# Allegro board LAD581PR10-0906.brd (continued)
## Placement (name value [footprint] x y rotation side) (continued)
CG339  1U_0402_6.3V4Z  [C_0402]  239.08 91.53 0 top
CG340  1U_0402_6.3V4Z  [C_0402]  219.03 130.69 90 top
CG341  1U_0402_6.3V4Z  [C_0402]  186.26 130.12 90 top
CG342  1U_0402_6.3V4Z  [C_0402]  220.11 129.7 270 top
CG343  1U_0402_6.3V4Z  [C_0402]  241.31 98.88 90 top
CG344  22U_0603_6.3V6M  [C_0603]  243.35 78.26 90 bottom
CG345  10U_0402_6.3V4Z  [C_0402]  221.32 140.23 180 top
CG346  10U_0402_6.3V4Z  [C_0402]  185.18 133.11 90 top
CG347  10U_0402_6.3V4Z  [C_0402]  238.53 106.01 180 top
CG348  1U_0402_6.3V4Z  [C_0402]  187.4 131.08 90 top
CG349  1U_0402_6.3V4Z  [C_0402]  242.39 94.59 270 top
CG350  1U_0402_6.3V4Z  [C_0402]  204.67 138.25 90 top
CG351  1U_0402_6.3V4Z  [C_0402]  237.43 80.29 0 top
CG352  1U_0402_6.3V4Z  [C_0402]  222.14 130.69 90 top
CG353  1U_0402_6.3V4Z  [C_0402]  185.31 130.12 90 top
CG354  1U_0402_6.3V4Z  [C_0402]  237.89 126.15 270 top
CG355  1U_0402_6.3V4Z  [C_0402]  221.12 129.7 270 top
CG356  1U_0402_6.3V4Z  [C_0402]  239.1 97.94 180 top
CG357  1U_0402_6.3V4Z  [C_0402]  186.39 133.9 270 top
CG358  1U_0402_6.3V4Z  [C_0402]  219.03 129.7 270 top
CG359  1U_0402_6.3V4Z  [C_0402]  220.28 134.64 0 top
CG360  1U_0402_6.3V4Z  [C_0402]  205.56 138.25 90 top
CG361  1U_0402_6.3V4Z  [C_0402]  243.61 77.05 180 top
CG362  1U_0402_6.3V4Z  [C_0402]  221.06 133.7 270 top
CG363  1U_0402_6.3V4Z  [C_0402]  184.22 136.87 0 top
CG364  22U_0603_6.3V6M  [C_0603]  229.88 130.01 270 bottom
CG365  10U_0402_6.3V4Z  [C_0402]  240.63 124.67 180 top
CG366  10U_0402_6.3V4Z  [C_0402]  239.47 105.93 90 top
CG367  10U_0402_6.3V4Z  [C_0402]  238.53 106.89 180 top
CG368  1U_0402_6.3V4Z  [C_0402]  185.26 131.91 180 top
CG369  1U_0402_6.3V4Z  [C_0402]  188.53 137.12 0 top
CG370  1U_0402_6.3V4Z  [C_0402]  234.19 125.63 0 top
CG371  1U_0402_6.3V4Z  [C_0402]  186.01 138.38 90 top
CG372  1U_0402_6.3V4Z  [C_0402]  221.12 130.69 90 top
CG373  1U_0402_6.3V4Z  [C_0402]  202.95 137.12 0 top
CG374  1U_0402_6.3V4Z  [C_0402]  240.63 123.72 180 top
CG375  1U_0402_6.3V4Z  [C_0402]  187.47 130.15 270 top
CG376  1U_0402_6.3V4Z  [C_0402]  240.63 122.83 180 top
CG377  1U_0402_6.3V4Z  [C_0402]  234.95 100.16 0 top
CG378  1U_0402_6.3V4Z  [C_0402]  240.37 98.83 180 top
CG379  1U_0402_6.3V4Z  [C_0402]  241.05 89.81 0 top
CG380  1U_0402_6.3V4Z  [C_0402]  204.99 136.22 90 top
CG381  1U_0402_6.3V4Z  [C_0402]  238.77 123.52 90 top
CG382  1U_0402_6.3V4Z  [C_0402]  220.11 133.7 270 top
CG383  1U_0402_6.3V4Z  [C_0402]  237.9 99.72 180 top
CG384  0.1U_0402_10V7K  [C_0402]  123.74 158.37 180 bottom
CG385  10U_0402_6.3V6M  [C_0402]  194.97 75.51 90 top
CG386  0.1U_0402_10V7K  [C_0402]  164.37 67.72 180 top
CG388  22U_0603_6.3V6M  [C_0603]  196.48 129.18 270 bottom
CG389  22U_0603_6.3V6M  [C_0603]  195.34 133.12 0 bottom
CG390  22U_0603_6.3V6M  [C_0603]  196.74 139.47 90 bottom
CG391  10U_0402_6.3V4Z  [C_0402]  203.99 129.82 180 top
CG392  10U_0402_6.3V4Z  [C_0402]  205.37 132.04 0 top
CG393  10U_0402_6.3V4Z  [C_0402]  203.2 134.77 0 top
CG394  1U_0402_6.3V4Z  [C_0402]  205.37 130.91 270 top
CG395  1U_0402_6.3V4Z  [C_0402]  205.63 135.22 0 top
CG396  1U_0402_6.3V4Z  [C_0402]  219.36 136.42 180 top
CG397  1U_0402_6.3V4Z  [C_0402]  203.98 131.74 270 top
CG398  1U_0402_6.3V4Z  [C_0402]  201.63 137.25 180 top
CG399  1U_0402_6.3V4Z  [C_0402]  205.37 133.18 90 top
CG400  1U_0402_6.3V4Z  [C_0402]  203.91 132.87 90 top
CG401  1U_0402_6.3V4Z  [C_0402]  219.29 137.37 180 top
CG402  1U_0402_6.3V4Z  [C_0402]  204.69 141.88 180 top
CG403  1U_0402_6.3V4Z  [C_0402]  204.67 141.01 270 top
CG404  22U_0603_6.3V6M  [C_0603]  231.15 122.77 180 bottom
CG405  22U_0603_6.3V6M  [C_0603]  234.14 108.2 0 top
CG406  22U_0603_6.3V6M  [C_0603]  180.99 144.68 0 bottom
CG407  10U_0402_6.3V4Z  [C_0402]  238.95 99.72 0 top
CG408  10U_0402_6.3V4Z  [C_0402]  238.58 108.43 0 top
CG409  10U_0402_6.3V4Z  [C_0402]  234.04 121.22 90 top
CG410  1U_0402_6.3V4Z  [C_0402]  239.84 114.27 0 top
CG411  1U_0402_6.3V4Z  [C_0402]  236.06 124.62 0 top
CG412  1U_0402_6.3V4Z  [C_0402]  236.06 125.54 0 top
CG413  1U_0402_6.3V4Z  [C_0402]  234.19 124.65 0 top
CG414  1U_0402_6.3V4Z  [C_0402]  240.95 97.94 180 top
CG415  1U_0402_6.3V4Z  [C_0402]  236.82 98.83 180 top
CG416  1U_0402_6.3V4Z  [C_0402]  234.01 113.04 90 top
CG417  1U_0402_6.3V4Z  [C_0402]  234.13 98.89 0 top
CG418  1U_0402_6.3V4Z  [C_0402]  236.06 126.44 0 top
CG419  1U_0402_6.3V4Z  [C_0402]  236.04 123.7 0 top
CG420  22U_0603_6.3V6M  [C_0603]  230.96 87.65 180 bottom
CG421  22U_0603_6.3V6M  [C_0603]  237.69 106.45 0 bottom
CG422  22U_0603_6.3V6M  [C_0603]  178.13 142.01 270 bottom
CG423  10U_0402_6.3V4Z  [C_0402]  241.7 78.83 90 top
CG424  10U_0402_6.3V4Z  [C_0402]  238.9 88.68 270 top
CG425  10U_0402_6.3V4Z  [C_0402]  236.81 73.56 0 top
CG426  1U_0402_6.3V4Z  [C_0402]  239.92 80.8 0 top
CG427  1U_0402_6.3V4Z  [C_0402]  242.91 86.19 180 top
CG428  1U_0402_6.3V4Z  [C_0402]  243.47 78.82 90 top
CG429  1U_0402_6.3V4Z  [C_0402]  240.22 86.19 0 top
CG430  1U_0402_6.3V4Z  [C_0402]  239.92 79.91 0 top
CG431  1U_0402_6.3V4Z  [C_0402]  242.58 78.83 90 top
CG432  1U_0402_6.3V4Z  [C_0402]  238.25 86.19 0 top
CG433  1U_0402_6.3V4Z  [C_0402]  242.46 76.1 270 top
CG434  1U_0402_6.3V4Z  [C_0402]  236.81 72.6 0 top
CG435  1U_0402_6.3V4Z  [C_0402]  237.44 79.4 0 top
CG436  0.1U_0402_16V4Z~D  [C_0402]  174.72 61.49 180 bottom
CG437  0.1U_0402_16V4Z~D  [C_0402]  174.74 60.6 180 bottom
CG438  0.1U_0201_6.3V6K  [C_0201]  93.13 68.41 0 top
CG439  0.1U_0201_6.3V6K  [C_0201]  95.73 68.22 0 top
CG440  0.1U_0201_6.3V6K  [C_0201]  189.66 76.03 180 top
CG442  0.01U_0402_16V  [C_0402]  186.56 57.67 270 top
CG443  0.01U_0402_16V  [C_0402]  182.31 56.36 0 top
CG444  0.1U_0201_6.3V6K  [C_0201]  90.78 67.52 0 top
CG483  0.1U_0201_6.3V6K  [C_0201]  185.87 66.85 180 bottom
CG487  0.1U_0402_10V7K  [C_0402]  191.52 68.55 180 bottom
CH1  10P_0402_50V8J~D  [C_0402]  316.37 80.05 270 top
CH2  0.1U_0402_16V4Z~D  [C_0402]  314.73 84.14 180 top
CH3  0.1U_0402_10V7K  [C_0402]  177.04 46.19 0 top
CH4  0.1U_0402_10V7K  [C_0402]  170.63 38.06 0 top
CH45  8.2P_0402_50V  [C_0402]  185.04 50.17 90 bottom
CH46  8.2P_0402_50V  [C_0402]  185.04 49.24 270 bottom
CH47  15P_0402_50V  [C_0402]  158.85 56.58 180 bottom
CH48  15P_0402_50V  [C_0402]  159.73 56.58 0 bottom
CH49  0.1U_0402_16V7K~D  [C_0402]  186.74 25.45 0 bottom
CH52  1U_0603_10V6K~D  [C_0603]  181.75 45.32 270 top
CH53  1U_0603_10V6K~D  [C_0603]  182.96 50.57 0 top
CH70  0.1U_0402_10V7K~D  [C_0402]  180.59 39.7 0 top
CH80  1U_0402_6.3V6K~D  [C_0402]  177.99 42.15 180 top
CH82  1U_0402_6.3V6K~D  [C_0402]  169.11 45.93 90 top
CH100  0.022U_0402_25V7K  [C_0402]  122.99 27.48 0 top
CH101  0.022U_0402_25V7K  [C_0402]  125.67 43.47 90 top
CH102  10U_0603_6.3V6M~D  [C_0603]  138.53 96.67 270 top
CH103  10U_0603_6.3V6M~D  [C_0603]  138.53 99.08 270 top
CH104  10U_0603_6.3V6M~D  [C_0603]  138.42 101.48 90 top
CH105  1U_0402_6.3V6K~D  [C_0402]  143.09 104.89 270 top
CH106  1U_0402_6.3V6K~D  [C_0402]  141.82 104.9 270 top
CH107  1U_0402_6.3V6K~D  [C_0402]  138.46 104.71 0 top
CH108  1U_0402_6.3V6K~D  [C_0402]  138.67 106.01 180 top
CH109  1U_0402_6.3V6K~D  [C_0402]  140.36 107.87 0 top
CH110  1U_0402_6.3V6K~D  [C_0402]  138.38 103.81 0 top
CH118  22U_0603_6.3V6M  [C_0603]  116.5 91.97 90 top
CH119  10U_0603_6.3V6M~D  [C_0603]  121.24 91.85 90 top
CH120  22U_0603_6.3V6M  [C_0603]  141.98 90.58 0 top
CH121  22U_0603_6.3V6M  [C_0603]  119.13 74.5 0 top
CH122  10U_0603_6.3V6M~D  [C_0603]  122.97 91.34 90 top
CH123  10U_0603_6.3V6M~D  [C_0603]  119.13 73.23 0 top
CH124  22U_0603_6.3V6M  [C_0603]  114.85 91.97 90 top
CH125  10U_0603_6.3V6M~D  [C_0603]  126.61 90.67 90 top
CH126  10U_0603_6.3V6M~D  [C_0603]  138.75 72.34 0 top
CH127  10U_0603_6.3V6M~D  [C_0603]  135.73 91.27 90 top
CH128  10U_0603_6.3V6M~D  [C_0603]  119.13 71.96 0 top
CH129  22U_0805_6.3V6M~D  [C_0805]  138.63 75.58 0 top
CH130  22U_0805_6.3V6M~D  [C_0805]  138.63 73.86 0 top
CH131  22U_0805_6.3V6M~D  [C_0805]  124.05 72.33 180 top
CH132  22U_0805_6.3V6M~D  [C_0805]  124.05 74.17 180 top
CH173  0.1U_0402_10V7K  [C_0402]  177.99 41.26 180 top
CH174  0.1U_0402_10V  [C_0402]  175.65 48.52 90 top
CH175  0.1U_0402_10V  [C_0402]  180.91 56.29 0 bottom
CH176  1U_0402_6.3V6K~D  [C_0402]  179.31 38.75 180 top
CH177  22U_0805_6.3V6M~D  [C_0805]  168.77 55.47 0 bottom
CH178  22U_0805_6.3V6M~D  [C_0805]  165.91 55.48 0 bottom
CH179  1U_0402_6.3V6K~D  [C_0402]  164.92 55.02 90 bottom
CH180  1U_0402_6.3V6K~D  [C_0402]  163.2 42.31 90 top
CH181  22U_0805_6.3V6M~D  [C_0805]  158.72 39.02 180 top
CH182  22U_0805_6.3V6M~D  [C_0805]  158.72 40.8 180 top
CH183  1U_0402_6.3V6K~D  [C_0402]  167.52 39.67 270 top
CH184  22U_0805_6.3V6M~D  [C_0805]  158.67 42.56 180 top
CH185  1U_0402_6.3V6K~D  [C_0402]  171.41 43.66 180 top
CH186  0.1U_0402_10V7K  [C_0402]  179.28 43.58 180 top
CH187  1U_0402_6.3V6K~D  [C_0402]  182.3 52.48 0 top
CH188  1U_0402_6.3V6K~D  [C_0402]  171.52 46.88 90 top
CH189  0.1U_0402_10V7K  [C_0402]  175.65 50.87 90 top
CH190  0.1U_0402_10V7K  [C_0402]  171.39 32.68 270 top
CH191  0.1U_0402_10V7K  [C_0402]  174.95 32.37 270 top
CH192  0.1U_0402_10V7K  [C_0402]  180.84 29.54 0 top
CH193  0.1U_0402_16V7K~D  [C_0402]  145.61 91.85 0 top
CH194  0.1U_0402_16V7K~D  [C_0402]  102.76 105.83 270 top
CH195  0.1U_0402_16V7K~D  [C_0402]  102.76 107.86 270 top
CH197  0.1U_0402_10V7K  [C_0402]  93.71 75.02 180 top
CH200  0.1U_0402_10V7K  [C_0402]  178.38 36.29 270 top
CH201  0.1U_0201_6.3V6K  [C_0201]  181.69 34.28 90 top
CH202  0.22U_0201_6.3V  [C_0201]  224.4 38.81 180 top
CH203  0.22U_0201_6.3V  [C_0201]  224.4 39.75 180 top
CH204  0.22U_0201_6.3V  [C_0201]  227.47 15.88 180 top
CH205  0.22U_0201_6.3V  [C_0201]  227.47 14.94 180 top
CH206  0.22U_0201_6.3V  [C_0201]  227.47 19.37 180 top
CH207  0.22U_0201_6.3V  [C_0201]  227.47 18.43 180 top
CH208  0.22U_0201_6.3V  [C_0201]  224.41 41.8 180 top
CH209  0.22U_0201_6.3V  [C_0201]  224.41 42.74 180 top
CH210  0.22U_0201_6.3V  [C_0201]  223.46 33.75 0 top
CH211  0.22U_0201_6.3V  [C_0201]  223.46 32.81 0 top
CH212  0.22U_0201_6.3V  [C_0201]  223.5 36.74 0 top
CH213  0.22U_0201_6.3V  [C_0201]  223.5 35.8 0 top
CH214  0.22U_0201_6.3V  [C_0201]  221.6 15.27 180 bottom
CH215  0.22U_0201_6.3V  [C_0201]  221.6 14.69 180 bottom
CH216  0.22U_0201_6.3V  [C_0201]  221.6 14.11 180 bottom
CH217  0.22U_0201_6.3V  [C_0201]  221.6 13.51 180 bottom
CI38  0.1U_0402_10V6K  [C_0402]  132.21 165.99 90 bottom
CI39  0.1U_0402_10V6K  [C_0402]  133.1 165.99 90 bottom
CL1  0.1U_0402_16V7K  [C_0402]  197.32 145.5 180 bottom
CL2  0.1U_0402_16V7K  [C_0402]  197.32 144.61 180 bottom
CL3  0.1U_0402_16V7K  [C_0402]  196.42 148.86 180 bottom
CL4  0.1U_0402_16V7K  [C_0402]  196.42 149.75 180 bottom
CL5  1U_0402_6.3V6K~D  [C_0402]  202.12 152.36 270 top
CL6  0.1U_0402_16V7K~D  [C_0402]  203.14 152.55 0 top
CL7  0.1U_0402_16V7K~D  [C_0402]  202.33 145.52 270 bottom
CL8  18P_0402_50V8J  [C_0402]  203.47 153.92 180 bottom
CL9  22P_0402_50V8J  [C_0402]  200.71 153.92 0 bottom
CL11  1000P_0402_50V7K~D  [C_0402]  197.3 153.61 90 bottom
CL12  0.1U_0402_16V7K~D  [C_0402]  196.41 153.61 90 bottom
CL13  1U_0402_6.3V6K~D  [C_0402]  196.66 152.24 270 bottom
CL14  10U_0603_6.3V6M~D  [C_0603]  195.52 152.22 270 bottom
CL15  10U_0603_6.3V6M~D  [C_0603]  195.34 153.69 90 bottom
CL16  0.1U_0402_16V7K~D  [C_0402]  203.53 148.69 270 top
CL17  1U_0402_6.3V6K~D  [C_0402]  203.84 149.76 180 top
CL18  1U_0402_6.3V6K~D  [C_0402]  201.24 152.36 270 top
CL19  0.1U_0402_16V7K~D  [C_0402]  200.35 152.36 270 top
CL20  0.1U_0402_16V7K~D  [C_0402]  198.12 148.74 0 top
CL21  1U_0402_6.3V6K~D  [C_0402]  198.7 147.73 315 top
CL22  4.7U_0603_6.3V6K~D  [C_0603]  196.74 149.27 180 top
CL23  0.1U_0402_16V7K~D  [C_0402]  198.07 146.07 0 top
CL24  0.1U_0402_16V7K~D  [C_0402]  203.93 151.09 180 top
CL25  0.1U_0402_16V7K~D  [C_0402]  203.54 146.39 180 top
CL27  470P_0402_50V7K  [C_0402]  208.62 159.54 180 bottom
CL28  470P_0402_50V7K  [C_0402]  231.83 158.19 0 bottom
CL29  470P_0402_50V7K  [C_0402]  231.83 160.1 0 bottom
CL30  10P_1808_3KV7K~D  [C_1808]  229.52 157.38 180 bottom
CL31  470P_0402_50V7K  [C_0402]  231.83 162.32 0 bottom
CL32  1000P_0402_50V7K~D  [C_0402]  210.98 145.1 90 top
CL33  0.1U_0402_16V7K~D  [C_0402]  213.27 146.01 270 top
CL34  1000P_0402_50V7K~D  [C_0402]  212.38 145.1 90 top
CL35  0.1U_0402_16V7K~D  [C_0402]  210.1 146.01 270 top
CL36  1000P_0402_50V7K~D  [C_0402]  220.94 145.06 90 top
CL37  0.1U_0402_16V7K~D  [C_0402]  220.08 145.98 270 top
CL38  1000P_0402_50V7K~D  [C_0402]  218.74 145.06 90 top
CL39  0.1U_0402_16V7K~D  [C_0402]  217.86 145.98 270 top
CL40  4.7U_0805_10V4Z  [C_0805]  190.53 150.26 180 bottom
CL41  0.1U_0402_16V7K  [C_0402]  190.58 151.65 180 bottom
CL42  0.1U_0402_16V7K  [C_0402]  191.9 148.93 270 bottom
CL43  1U_0402_6.3V6K~D  [C_0402]  198.43 151.46 0 top
CL44  0.1U_0402_16V7K~D  [C_0402]  198.12 150.01 0 top
CLRP1  SHORT PADS  [SHORTPADS]  144.22 17.3 180 bottom
CM9  0.1U_0402_10V7K  [C_0402]  104.59 154.12 90 bottom
CM10  0.1U_0402_10V7K  [C_0402]  294.54 52.62 180 top
CM11  4.7U_0805_10V4Z  [C_0805]  292.22 61.17 90 top
CM12  22U_0603_6.3V6M~D  [C_0603]  294.5 51.48 180 top
CM13  0.1U_0402_10V7K~D  [C_0402]  294.51 50.4 180 top
CM14  22U_0603_6.3V6M~D  [C_0603]  294.53 67.99 180 top
CM15  0.1U_0402_10V7K~D  [C_0402]  294.51 66.91 180 top
CM16  0.1U_0402_10V7K  [C_0402]  92.97 151.89 90 bottom
CM17  0.1U_0402_10V7K  [C_0402]  92.08 151.89 90 bottom
CM18  0.1U_0402_10V7K  [C_0402]  89.41 151.89 90 bottom
CM19  22U_0603_6.3V6M  [C_0603]  86.17 151.72 90 bottom
CM20  0.1U_0402_10V7K  [C_0402]  89.22 142.9 270 bottom
CM21  1U_0402_6.3V  [C_0402]  86.87 142.78 270 bottom
CM23  0.1U_0402_10V7K  [C_0402]  129.48 167.92 270 bottom
CM29  10U_0603_6.3V6M  [C_0603]  95.6 145.81 180 bottom
CM30  1U_0402_6.3V  [C_0402]  95.71 148.92 180 bottom
CM31  10U_0603_6.3V6M  [C_0603]  95.6 147.59 180 bottom
CM32  0.1U_0402_10V7K  [C_0402]  101.6 145.19 270 bottom
CM33  1U_0402_6.3V  [C_0402]  95.71 149.81 180 bottom
CM34  0.1U_0402_10V7K  [C_0402]  108.9 149.27 0 bottom
CM35  0.1U_0402_10V7K  [C_0402]  100.08 145.19 270 bottom
CM36  0.1U_0402_10V7K  [C_0402]  101.99 154.12 90 bottom
CM62  0.22U_0201_6.3V6M  [C_0201]  104.03 142.48 90 bottom
CM63  0.22U_0201_6.3V6M  [C_0201]  105.93 144.45 90 bottom
CM64  0.22U_0201_6.3V6M  [C_0201]  103.33 144.45 90 bottom
CM65  0.22U_0201_6.3V6M  [C_0201]  102.69 144.45 90 bottom
CM66  0.22U_0201_6.3V6M  [C_0201]  105.3 144.45 90 bottom
CM67  0.22U_0201_6.3V6M  [C_0201]  107.27 142.48 90 bottom
CM68  0.22U_0201_6.3V6M  [C_0201]  104.66 142.48 90 bottom
CM69  0.22U_0201_6.3V6M  [C_0201]  106.63 142.48 90 bottom
CM70  0.1U_0402_10V7K  [C_0402]  115.45 165.67 90 bottom
CM98  0.01U_0402_16V7K  [C_0402]  88.33 154.18 90 bottom
CM99  0.01U_0402_16V7K  [C_0402]  87.32 154.18 90 bottom
CN9  1U_0402_10V6K  [C_0402]  293.23 63.92 90 top
CN23  0.1U_0402_16V7K  [C_0402]  296.72 56.24 180 top
CN24  0.1U_0402_16V7K  [C_0402]  296.72 57.13 180 top
CN25  1U_0402_10V6K  [C_0402]  292.81 55.47 270 top
CPU1  SKL-H_BGA1440  [SKL-H_BGA_1440P-T]  143.46 85.09 270 bottom
CT1  0.22U_0201_6.3V  [C_0201]  156.54 153.35 180 top
CT2  0.22U_0201_6.3V  [C_0201]  156.54 153.92 180 top
CT3  0.22U_0201_6.3V  [C_0201]  156.54 151.06 180 top
CT4  0.22U_0201_6.3V  [C_0201]  156.54 155.06 180 top
CT5  0.22U_0201_6.3V  [C_0201]  156.54 157.35 180 top
CT6  0.1U_0201_6.3V6K  [C_0201]  145.62 148.17 90 top
CT7  0.1U_0201_6.3V6K  [C_0201]  146.19 148.17 90 top
CT8  0.1U_0201_6.3V6K  [C_0201]  147.33 148.17 90 top
CT9  0.1U_0201_6.3V6K  [C_0201]  146.76 148.17 90 top
CT10  0.1U_0201_6.3V6K  [C_0201]  148.47 148.17 90 top
CT11  0.1U_0201_6.3V6K  [C_0201]  149.62 148.17 90 top
CT12  0.22U_0201_6.3V  [C_0201]  156.54 154.49 180 top
CT13  0.22U_0201_6.3V  [C_0201]  156.54 152.78 180 top
CT14  0.22U_0201_6.3V  [C_0201]  156.54 152.2 180 top
CT15  0.22U_0201_6.3V  [C_0201]  156.54 150.49 180 top
CT16  0.22U_0201_6.3V  [C_0201]  156.54 151.63 180 top
CT18  0.22U_0201_6.3V  [C_0201]  156.54 155.63 180 top
CT21  0.22U_0201_6.3V  [C_0201]  156.54 157.92 180 top
CT23  0.1U_0201_6.3V6K  [C_0201]  147.9 148.17 90 top
CT24  0.1U_0201_6.3V6K  [C_0201]  149.05 148.17 90 top
CT25  0.1U_0201_6.3V6K  [C_0201]  147.58 144.19 90 bottom
CT26  0.1U_0201_6.3V6K  [C_0201]  147.01 144.19 90 bottom
CT27  0.1U_0201_6.3V6K  [C_0201]  150.76 148.17 90 top
CT28  0.1U_0201_6.3V6K  [C_0201]  150.19 148.17 90 top
CT29  0.1U_0201_6.3V6K  [C_0201]  151.9 148.17 90 top
CT30  0.1U_0201_6.3V6K  [C_0201]  151.33 148.17 90 top
CT31  0.1U_0201_6.3V6K  [C_0201]  153.05 148.17 90 top
CT32  0.1U_0201_6.3V6K  [C_0201]  152.48 148.17 90 top
CT33  0.1U_0201_6.3V6K  [C_0201]  154.19 148.17 90 top
CT34  0.1U_0201_6.3V6K  [C_0201]  153.62 148.17 90 top
CT35  0.1U_0201_6.3V6K  [C_0201]  149.55 144.19 90 bottom
CT36  0.1U_0201_6.3V6K  [C_0201]  150.14 144.18 90 bottom
CT37  27P_0402_50V8J  [C_0402]  158.48 160.32 90 top
CT38  27P_0402_50V8J  [C_0402]  158.48 159.46 270 top
CT39  0.22U_0201_6.3V  [C_0201]  149.24 165.13 270 top
CT40  0.22U_0201_6.3V  [C_0201]  148.67 165.13 270 top
CT41  0.22U_0201_6.3V  [C_0201]  150.7 165.13 270 top
CT42  0.22U_0201_6.3V  [C_0201]  151.27 165.13 270 top
CT43  0.1U_0201_6.3V6K  [C_0201]  150.97 148.44 90 bottom
CT44  0.1U_0201_6.3V6K  [C_0201]  150.4 148.44 90 bottom
CT45  0.1U_0201_6.3V6K  [C_0201]  134.23 145.23 225 bottom
CT46  0.1U_0201_6.3V6K  [C_0201]  146.88 153.32 270 bottom
CT47  1U_0201_6.3V6M  [C_0201]  146.27 158.36 270 bottom
CT48  1U_0201_6.3V6M  [C_0201]  150.37 154.44 45 bottom
CT49  1U_0201_6.3V6M  [C_0201]  143.93 162.54 180 top
CT50  10U_0402_6.3V6M  [C_0402]  144.39 163.34 180 top
CT51  10U_0402_6.3V6M  [C_0402]  144.39 164.23 180 top
CT52  10U_0402_6.3V6M  [C_0402]  144.42 165.11 180 top
CT53  10U_0402_6.3V6M  [C_0402]  144.43 166.01 180 top
CT54  1U_0201_6.3V6M  [C_0201]  155.93 151.11 0 bottom
CT55  1U_0201_6.3V6M  [C_0201]  153.39 154.46 0 bottom
CT56  1U_0201_6.3V6M  [C_0201]  151.43 153.3 0 bottom
CT57  1U_0201_6.3V6M  [C_0201]  155.93 151.68 0 bottom
CT58  1U_0201_6.3V6M  [C_0201]  155.93 150.54 0 bottom
CT59  1U_0201_6.3V6M  [C_0201]  149.48 155.95 270 bottom
CT60  1U_0201_6.3V6M  [C_0201]  150.05 153.21 270 bottom
CT61  1U_0201_6.3V6M  [C_0201]  147.58 155.75 270 bottom
CT62  1U_0201_6.3V6M  [C_0201]  146.79 156.42 180 bottom
CT63  1U_0201_6.3V6M  [C_0201]  150.73 158.46 0 bottom
CT64  1U_0201_6.3V6M  [C_0201]  149.53 157.89 180 bottom
CT65  1U_0201_6.3V6M  [C_0201]  148.41 159.69 90 bottom
CT66  1U_0201_6.3V6M  [C_0201]  148.99 159.69 90 bottom
CT67  1U_0201_6.3V6M  [C_0201]  149.56 159.69 90 bottom
CT68  1U_0201_6.3V6M  [C_0201]  147.59 156.39 90 bottom
CT69  1U_0201_6.3V6M  [C_0201]  150.13 159.69 90 bottom
CT70  1U_0201_6.3V6M  [C_0201]  153.39 155.03 0 bottom
CT71  1U_0201_6.3V6M  [C_0201]  153.39 155.6 0 bottom
CT72  1U_0201_6.3V6M  [C_0201]  152.22 154.81 270 bottom
CT73  47U_0603_6.3V6M  [C_0603]  137.1 161.18 180 bottom
CT74  47U_0603_6.3V6M  [C_0603]  137.1 159.84 180 bottom
CT75  47U_0603_6.3V6M  [C_0603]  137.1 158.51 180 bottom
CT77  1U_0201_6.3V6M  [C_0201]  155.37 148.74 180 top
CT78  1U_0201_6.3V6M  [C_0201]  147.46 153.31 270 bottom
CT79  1U_0201_6.3V6M  [C_0201]  149.48 154.15 90 bottom
CT80  1U_0201_6.3V6M  [C_0201]  148.28 154.54 90 bottom
CT81  10U_0402_6.3V6M  [C_0402]  159.64 157.23 0 top
CT82  10U_0402_6.3V6M  [C_0402]  159.64 156.34 0 top
CT83  1U_0201_6.3V6M  [C_0201]  159.83 157.96 0 top
CT84  1U_0201_6.3V6M  [C_0201]  158.41 157.62 180 top
CT85  1U_0201_6.3V6M  [C_0201]  152.01 156.41 90 bottom
CT86  1U_0201_6.3V6M  [C_0201]  150.76 157.1 90 bottom
CT88  0.1U_0402_10V6K  [C_0402]  120.68 144.32 180 bottom
CT90  22U_0603_6.3V6M  [C_0603]  132.28 145.76 270 bottom
CT91  22U_0603_6.3V6M  [C_0603]  131.07 145.75 270 bottom
CT92  22U_0603_6.3V6M  [C_0603]  130.18 146.83 0 bottom
CT93  22U_0603_6.3V6M  [C_0603]  130.18 148.03 0 bottom
CT94  0.47U_0402_25V6K  [C_0402]  161.32 172.87 180 top
CT95  0.47U_0402_25V6K  [C_0402]  156.67 171.35 0 top
CT96  0.47U_0402_25V6K  [C_0402]  159.59 170.78 0 top
CT97  0.47U_0402_25V6K  [C_0402]  157.65 172.82 180 top
CT98  2.2U_0603_16V6K  [C_0603]  121.43 149.69 180 bottom
CT99  4.7U_0603_10V6K  [C_0603]  122.44 146.46 270 bottom
CT100  4.7U_0603_10V6K  [C_0603]  123.83 152.74 90 top
CT101  1U_0402_6.3V6K  [C_0402]  120.98 152.99 180 bottom
CT102  1U_0201_6.3V6M  [C_0201]  120.85 153.82 180 bottom
CT103  10U_0402_6.3V6M  [C_0402]  121.19 150.72 180 bottom
CT104  0.22U_0402_10V4Z  [C_0402]  126.57 153.25 180 top
CT106  1U_0603_25V6K  [C_0603]  131.48 152.22 90 bottom
CT108  0.22U_0201_6.3V  [C_0201]  156.54 156.78 180 top
CT109  0.22U_0201_6.3V  [C_0201]  156.54 156.2 180 top
CT110  0.22U_0201_6.3V  [C_0201]  156.54 158.49 180 top
CT111  0.22U_0201_6.3V  [C_0201]  156.54 159.06 180 top
CT112  220P_0201_25V7K  [C_0201]  128.47 156.07 90 bottom
CT113  220P_0201_25V7K  [C_0201]  130.57 156.07 90 bottom
CU2  47U_0805_6.3V6M~D  [C_0805]  17.25 55.77 0 bottom
CU3  10U_0603_6.3V6M~D  [C_0603]  17.4 57.29 0 bottom
CU4  0.1U_0402_10V7K  [C_0402]  298.28 64.72 180 top
CU5  0.1U_0402_10V7K  [C_0402]  298.28 65.61 180 top
CU6  150U_B15G_6.3VM_R70M  [C_B15G]  17.69 53.3 0 bottom
CU7  0.1U_0402_10V7K  [C_0402]  18.11 46.12 180 top
CU10  47U_0805_6.3V6M~D  [C_0805]  303.35 59.38 270 top
CU11  10U_0603_6.3V6M~D  [C_0603]  304.49 61.96 180 top
CU12  0.1U_0402_10V7K  [C_0402]  22.47 56.91 0 top
CU13  0.1U_0402_10V7K  [C_0402]  22.47 56.02 0 top
CU16  0.1U_0402_16V7K  [C_0402]  298.53 63.85 270 top
CU17  0.1U_0402_16V7K  [C_0402]  303.1 63.94 270 top
CU18  0.47U_0402_25V6K  [C_0402]  312.96 41.01 0 top
CU19  0.47U_0402_25V6K  [C_0402]  312.96 40.06 0 top
CU20  0.47U_0402_25V6K  [C_0402]  312.96 45.01 0 top
CU21  0.47U_0402_25V6K  [C_0402]  312.96 44.06 0 top
CU26  0.1U_0402_16V7K  [C_0402]  63.9 59.19 90 top
CU27  2.2U_0603_6.3V6K  [C_0603]  68.9 59.83 90 top
CU28  0.1U_0402_16V7K  [C_0402]  69.21 62.81 0 top
CU29  0.1U_0402_16V7K  [C_0402]  66.92 61.86 0 top
CU30  0.1U_0402_10V7K  [C_0402]  300.8 40.75 180 bottom
CU31  0.1U_0402_10V7K  [C_0402]  300.8 41.7 180 bottom
CU32  2.2U_0603_25V6K  [C_0603]  299.15 43.13 90 top
CU33  47U_0603_6.3V6M  [C_0603]  291.03 42.25 90 top
CU34  0.1U_0402_16V7K  [C_0402]  292.17 42.48 90 top
CU35  0.1U_0402_16V7K  [C_0402]  292.17 39.33 270 top
CU37  10U_0805_25V6K  [C_0805]  300.74 43.23 90 top
CU38  0.1U_0402_10V7K  [C_0402]  300.82 39.13 180 bottom
CU39  0.1U_0402_10V7K  [C_0402]  300.82 38.24 180 bottom
CU40  150U_B15G_6.3VM_R70M  [C_B15G]  300.24 41.28 270 top
CU42  47U_0603_6.3V6M  [C_0603]  289.83 42.25 90 top
CU43  150U_B15G_6.3VM_R70M  [C_B15G]  300.87 59.49 270 top
CU44  47U_0603_6.3V6M  [C_0603]  288.62 42.25 90 top
CU45  0.1U_0402_10V7K  [C_0402]  298.78 59.16 270 top
CU46  0.1U_0402_10V7K  [C_0402]  298.46 61.11 90 top
CU47  0.1U_0402_10V7K  [C_0402]  18.62 52.41 0 top
CU48  10U_0402_6.3V6M  [C_0402]  297.83 60.16 270 top
CV1  0.1U_0201_6.3V6K  [C_0201]  115.58 157.91 270 top
CV2  0.1U_0201_6.3V6K  [C_0201]  116.16 157.91 270 top
CV3  0.1U_0201_6.3V6K  [C_0201]  116.6 156.45 270 top
CV4  0.1U_0201_6.3V6K  [C_0201]  117.17 156.45 270 top
CV5  4.7U_0805_10V4Z  [C_0805]  137.72 166.71 0 bottom
CV6  0.1U_0201_6.3V6K  [C_0201]  135.09 158.28 270 top
CV7  0.1U_0201_6.3V6K  [C_0201]  134.15 158.28 270 top
CV8  0.1U_0201_6.3V6K  [C_0201]  135.66 158.28 270 top
CV9  0.1U_0402_10V7K  [C_0402]  141.49 164.95 270 bottom
CV10  4.7U_0805_10V4Z  [C_0805]  142.28 166.71 180 bottom
CV11  0.1U_0201_6.3V6K  [C_0201]  133.58 158.28 270 top
CV12  0.1U_0201_6.3V6K  [C_0201]  132.65 158.26 270 top
CV13  0.1U_0201_6.3V6K  [C_0201]  132.08 158.26 270 top
CV14  0.1U_0603_25V7K  [C_0603]  123.05 156.49 270 top
CV15  1000P_0402_50V7K  [C_0402]  120.02 154.3 180 top
CV17  0.1U_0402_10V7K  [C_0402]  143.37 167.02 0 bottom
CV18  10U_0603_6.3V6M  [C_0603]  143.33 165.63 0 bottom
CV19  0.1U_0402_10V7K  [C_0402]  122.86 160.18 270 bottom
CV20  0.1U_0402_16V7K  [C_0402]  195.07 159.98 0 bottom
CV21  4.7U_0805_10V4Z  [C_0805]  120.41 159.58 180 bottom
CV23  0.1U_0201_6.3V6K  [C_0201]  195.05 161.06 0 bottom
CV24  0.1U_0201_6.3V6K  [C_0201]  188.9 152.93 180 bottom
CV25  0.1U_0201_6.3V6K  [C_0201]  188.9 153.5 180 bottom
CV26  0.1U_0201_6.3V6K  [C_0201]  198.52 162.86 90 top
CV27  0.1U_0201_6.3V6K  [C_0201]  197.88 162.86 90 top
CV28  0.1U_0201_6.3V6K  [C_0201]  200.67 162.86 90 top
CV29  0.1U_0201_6.3V6K  [C_0201]  200.36 159.98 90 bottom
CV30  0.1U_0201_6.3V6K  [C_0201]  201.31 162.86 90 top
CV31  0.1U_0201_6.3V6K  [C_0201]  200.99 159.98 90 bottom
CV32  0.1U_0201_6.3V6K  [C_0201]  204.61 162.86 90 top
CV33  0.1U_0201_6.3V6K  [C_0201]  203.98 162.86 90 top
CV34  10U_0402_6.3V6M  [C_0402]  204.22 160.55 0 bottom
CV35  0.1U_0201_6.3V6K  [C_0201]  204.38 161.31 0 bottom
CV372  10P_0402_50V8J  [C_0402]  136.92 165.07 270 bottom
CV373  10P_0402_50V8J  [C_0402]  142.38 164.95 270 bottom
CV374  10P_0402_50V8J  [C_0402]  126.46 156.27 90 top
CV375  10P_0402_50V8J  [C_0402]  124.09 156.51 0 top
CV416  0.1U_0201_6.3V6K  [C_0201]  153.41 102.7 180 bottom
CV417  0.1U_0201_6.3V6K  [C_0201]  153.41 103.28 180 bottom
CV418  0.1U_0201_6.3V6K  [C_0201]  153.41 103.97 180 bottom
CV419  0.1U_0201_6.3V6K  [C_0201]  153.41 104.61 180 bottom
CV420  0.1U_0201_6.3V6K  [C_0201]  153.41 105.31 180 bottom
CV421  0.1U_0201_6.3V6K  [C_0201]  153.41 105.94 180 bottom
CV422  0.1U_0201_6.3V6K  [C_0201]  153.41 106.64 180 bottom
CV423  0.1U_0201_6.3V6K  [C_0201]  153.41 107.28 180 bottom
CV424  0.1U_0201_6.3V6K  [C_0201]  158.76 114.1 90 bottom
CV425  0.1U_0201_6.3V6K  [C_0201]  158.19 114.1 90 bottom
CV426  0.1U_0201_6.3V6K  [C_0201]  151.82 107.85 180 bottom
CV427  0.1U_0201_6.3V6K  [C_0201]  151.82 108.48 180 bottom
CV428  0.1U_0201_6.3V6K  [C_0201]  153.41 109.12 180 bottom
CV429  0.1U_0201_6.3V6K  [C_0201]  153.41 109.75 180 bottom
CV430  0.1U_0201_6.3V6K  [C_0201]  151.82 110.45 180 bottom
CV431  0.1U_0201_6.3V6K  [C_0201]  151.82 111.09 180 bottom
CV432  0.1U_0201_6.3V6K  [C_0201]  153.41 111.72 180 bottom
CV433  0.1U_0201_6.3V6K  [C_0201]  153.41 112.36 180 bottom
CV434  0.1U_0201_6.3V6K  [C_0201]  160.16 114.1 90 bottom
CV435  0.1U_0201_6.3V6K  [C_0201]  159.53 114.1 90 bottom
CV436  0.1U_0402_16V4Z~D  [C_0402]  156.24 113.45 180 bottom
CV437  0.1U_0402_16V4Z~D  [C_0402]  152.73 101 270 bottom
CV438  2.2U_0402_6.3V6M~D  [C_0402]  161.98 104.66 0 bottom
CV484  0.1U_0402_16V4Z~D  [C_0402]  172.1 128.35 90 bottom
CV1056  0.1U_0402_16V7K  [C_0402]  164.72 163.86 270 bottom
CV1057  0.1U_0201_6.3V6K  [C_0201]  184.89 157.14 270 bottom
CV1058  0.1U_0201_6.3V6K  [C_0201]  184.25 157.14 270 bottom
CV1059  0.1U_0201_6.3V6K  [C_0201]  187.3 157.21 270 bottom
CV1060  0.1U_0201_6.3V6K  [C_0201]  187.93 157.21 270 bottom
CV1061  0.1U_0201_6.3V6K  [C_0201]  181.71 157.14 270 bottom
CV1062  0.1U_0201_6.3V6K  [C_0201]  182.35 157.14 270 bottom
CV1063  0.1U_0201_6.3V6K  [C_0201]  179.61 157.33 270 bottom
CV1064  0.1U_0201_6.3V6K  [C_0201]  180.25 157.33 270 bottom
CV1068  10U_0603_6.3V6M~D  [C_0603]  186.89 162.97 0 top
CV1069  0.1U_0201_6.3V6K  [C_0201]  187.05 163.98 0 top
CX1  0.1U_0402_16V7K  [C_0402]  197.81 160.87 270 bottom
CX2  0.1U_0402_16V7K  [C_0402]  169.87 166.52 270 bottom
DA1  -  [BAT54C-7-F_SOT23-3]  32.74 33.1 270 top
DA2  BAT54AW_SOT323-3~D  [BAT54AW_SOT323-3]  37.33 41.68 90 top
DA3  BAT54AW_SOT323-3~D  [BAT54AW_SOT323-3]  29.53 49.07 180 top
DA4  AZ5125-02S.R7G_SOT23-3  [AZ5125-02SPR7G_SOT23-3]  18.04 19.35 90 top
DA5  AZ5123-02S SOT23  [AZ5125-02SPR7G_SOT23-3]  18.2 19.28 270 bottom
DA6  AZ5125-02S.R7G_SOT23-3  [AZ5125-02SPR7G_SOT23-3]  16.12 33.38 270 top
DA7  AZ5125-02S.R7G_SOT23-3  [AZ5125-02SPR7G_SOT23-3]  39.51 9.98 90 top
DA8  AZ5125-02S.R7G_SOT23-3  [AZ5125-02SPR7G_SOT23-3]  39.51 6.01 90 top
DE1  SDMK0340L-7-F_SOD323-2~D  [SDMK0340L-7-F_SOD323-2]  257.38 49.05 90 top
DE2  -  [RB751V-40_SOD323-2]  111.66 20.15 0 top
DE3  -  [RB751V-40_SOD323-2]  111.47 22.19 0 top
DE4  -  [RB751V-40_SOD323-2]  111.08 23.98 0 top
DF1  -  [SDMK0340L-7-F_SOD323-2]  66.1 56.11 180 top
DF2  -  [SDMK0340L-7-F_SOD323-2]  243.66 85.3 270 bottom
DG1  -  [BAT54A-7-F_SOT23-3]  180.99 62.09 0 bottom
DG2  -  [RB751S40T1G_SOD523-2]  182.45 75.02 90 bottom
DG3  -  [RB751S40T1G_SOD523-2]  185.44 59.08 180 top
DG4  -  [RB751S40T1G_SOD523-2]  184.48 61.05 90 top
DG6  -  [RB751S40T1G_SOD523-2]  182.77 58.25 180 top
DG7  -  [RB751S40T1G_SOD523-2]  185.5 57.87 180 top
DG8  -  [RB751S40T1G_SOD523-2]  167.14 26.02 0 bottom
DG9  -  [RB751S40T1G_SOD523-2]  167.01 24.24 0 bottom
DH1  -  [RB751V-40_SOD323-2]  189.18 39.98 90 bottom
DT1  SDM10U45-7_SOD523-2~D  [SDM10U45-7_SOD523-2]  159.07 167.98 270 top
DT2  ESD8011MUT5G X3DFN2 ESD  [ESD108-B1-CSP0201_WLL-2-1-2]  156.41 168.93 180 bottom
DT3  ESD8011MUT5G X3DFN2 ESD  [ESD108-B1-CSP0201_WLL-2-1-2]  157.11 168.93 0 bottom
DT4  ESD8011MUT5G X3DFN2 ESD  [ESD108-B1-CSP0201_WLL-2-1-2]  154.38 167.16 180 bottom
DT5  ESD8011MUT5G X3DFN2 ESD  [ESD108-B1-CSP0201_WLL-2-1-2]  155.08 167.16 0 bottom
DT6  ESD8011MUT5G X3DFN2 ESD  [ESD108-B1-CSP0201_WLL-2-1-2]  162.7 166.97 0 top
DT7  ESD8011MUT5G X3DFN2 ESD  [ESD108-B1-CSP0201_WLL-2-1-2]  162.01 166.97 180 top
DT8  ESD8011MUT5G X3DFN2 ESD  [ESD108-B1-CSP0201_WLL-2-1-2]  162.71 166.97 0 bottom
DT9  ESD8011MUT5G X3DFN2 ESD  [ESD108-B1-CSP0201_WLL-2-1-2]  162.01 166.97 180 bottom
DT10  -  [TVWDF1004AD0_DFN9]  158.22 167.22 0 bottom
DT11  ESD8011MUT5G X3DFN2 ESD  [ESD108-B1-CSP0201_WLL-2-1-2]  158.23 165.85 0 top
DT12  ESD8011MUT5G X3DFN2 ESD  [ESD108-B1-CSP0201_WLL-2-1-2]  159.56 172.86 90 top
DT13  ESD8011MUT5G X3DFN2 ESD  [ESD108-B1-CSP0201_WLL-2-1-2]  161.21 168.71 90 top
DT14  ESD8011MUT5G X3DFN2 ESD  [ESD108-B1-CSP0201_WLL-2-1-2]  158.48 172.86 90 top
DT15  AZ4024-02S_SOT23-3~D  [PESD24VS2UT_SOT23-3]  155.11 168.64 270 top
DU1  -  [L30ESDL5V0C3-2_SOT23-3]  20.54 47.2 270 bottom
DU2  -  [TVWDF1004AD0_DFN9]  18.54 54.7 90 top
DU4  -  [L30ESDL5V0C3-2_SOT23-3]  302.99 69.42 90 top
DU5  -  [TVWDF1004AD0_DFN9]  302.14 66.86 270 top
DU8  -  [SDMK0340L-7-F_SOD323-2]  71.52 62.95 270 top
DU9  -  [SDMK0340L-7-F_SOD323-2]  65.54 63.22 0 top
DU11  -  [L30ESDL5V0C3-2_SOT23-3]  309.54 42.06 90 top
DU12  -  [L05ESDL5V0NA-4_SLP2510P8-10-9]  309.46 44.62 270 bottom
DU13  -  [L05ESDL5V0NA-4_SLP2510P8-10-9]  310.2 43.38 90 bottom
DU20  AZC199-02SPR7G_SOT23-3  [PSOT24C_SOT23-3]  305.61 46.06 270 top
DU21  AZC199-02SPR7G_SOT23-3  [PSOT24C_SOT23-3]  300.08 34.7 90 top
DV1  -  [RB751V-40_SOD323-2]  135.58 154.82 180 bottom
DV2  -  [L03ESDL5V0CG3-2_SOT-523-3]  130.85 157.21 0 top
DV4  -  [TVNST52302AB0_SOT523-3]  128.79 157.16 0 top
DV12  -  [SDM10U45-7_SOD523-2]  169.24 156.55 0 bottom
DV13  -  [SDM10U45-7_SOD523-2]  172.74 156.55 180 bottom
FD1  FIDUCAL  [FIDUCIAL_C40M80]  244.24 163.91 90 top
FD2  FIDUCIAL  [FIDUCIAL_C40M80]  49.04 5.68 180 bottom
FD3  FIDUCAL  [FIDUCIAL_C40M80]  42.88 5.8 0 top
FD4  FIDUCIAL  [FIDUCIAL_C40M80]  245.29 163.92 180 bottom
FV2  1.1A_6V_SPR-P110  [F_SPR-P110]  190.96 163.04 0 top
FV3  1.1A_6V_SPR-P110  [F_SPR-P110]  183.25 163.09 0 top
H1  -  [H_3P8]  211.3 68.4 0 top
H2  -  [H_3P8]  178.75 68.4 0 top
H3  -  [H_3P8]  228.55 150.3 0 top
H4  -  [H_3P8]  159.4 83.8 0 top
H5  -  [H_3P8]  90.4 85.4 0 top
H6  -  [H_3P8]  170.95 145.8 0 top
H7  -  [H_3P8]  114.45 147.3 0 top
H8  H_2P8  [H_2P8-G]  314.1 33 0 top
H9  H_2P8  [H_2P8-G]  314.1 51.6 0 top
H10  H_2P8  [H_2P8-G]  109.85 165.5 0 top
H11  H_2P8  [H_2P8-G]  315.2 58 0 top
H12  H_2P8  [H_2P8-G]  250.1 53.62 0 top
H13  H_2P8  [H_2P8-G]  220.65 8 0 top
H14  H_2P8  [H_2P8-G]  158.45 7.3 0 top
H15  H_2P8  [H_2P8-G]  159.63 74.48 0 top
H16  H_2P8  [H_2P8-G]  231.65 167.5 0 top
H17  H_2P8  [H_2P8-G]  168.42 172.1 0 top
H18  H_2P8  [H_2P8-G]  149.82 172.1 0 top
H19  -  [H_2P4X2P8]  108.15 171.51 0 top
H20  H_2P8  [H_2P8-G]  49.86 55.13 0 top
H21  H_2P9  [H_2P9-G]  30.15 6.5 0 top
H22  H_2P8  [H_2P8-G]  4 58 0 top
H23  H_2P8  [H_2P8-G]  24.15 6.5 0 top
H24  H_2P6  [H_2P6-G]  11 58 0 top
H25  -  [H_2P8X3P3]  237.8 164.5 90 top
H26  -  [H_3P2X2P7]  308.2 58 180 top
H27  -  [H_5P5]  254.85 74.48 0 top
H28  -  [H_3P2]  268.15 59.25 0 top
H29  -  [H_3P2]  307.45 35.8 0 top
H30  -  [H_3P1X3P5]  312.69 80.86 90 top
H31  -  [H_5P0N]  287.65 66.9 0 top
H32  -  [H_5P0N]  287.1 58.2 0 top
H33  -  [H_5P0N]  237.6 35.78 0 top
H34  -  [H_5P0N]  241.87 10.16 0 top
J4  -  [JUMP_43X79]  59.76 55.56 180 bottom
J5  -  [JUMP_43X79]  58.18 64.84 270 bottom
J6  -  [JUMP_43X79]  155.59 59.5 270 top
JACK1  YUQIU_PJ741-F07J1BE-C  [YUQIU_PJ741-F07J1BE-C_6P-T]  11.49 12.81 90 bottom
JACK2  YUQIU_PJ741-F07J1BE-C  [YUQIU_PJ741-F07J1BE-C_6P-T]  11.51 25.45 90 bottom
JCDRA  TE_2260531-1  [TE_2260531-1_46P-T]  119.1 170.75 0 bottom
JDIMM1  DEREN_40-42271-26001RHF  [DEREN_40-42271-26001RHF_260P-T]  82.02 49.9 0 bottom
JDIMM2  DEREN_40-42261-26001RHF  [DEREN_40-42261-26001RHF_260P-T]  82.03 37.1 180 bottom
JDP  ACON_MAR2F-20K1800  [ACON_MAR2F-20K1800_20P]  198.32 167.14 180 bottom
JEC  ACES_50521-0084N-P01  [ACES_50521-0084N-P01_8P]  103.74 23.15 180 bottom
JEDP  ACES_50473-0400M-P01  [ACES_50473-0400M-002_40P-T]  138.6 159.93 180 top
JELC  AMPHE_G846A06201EU  [AMPHE_G846A06201EU_6P-T]  221.38 30.63 270 bottom
JFAN1  CVILU_CI1804M1VRA-NH  [CVILU_CI1804M1VRA-NH_4P]  64.49 63.3 207.5 bottom
JFAN2  CVILU_CI1804M1VRA-NH  [CVILU_CI1804M1VRA-NH_4P]  245.53 88.25 117.5 bottom
JHDMI  ACON_HMRA3-AK1L0C  [ACON_HMRA3-AK1L0C_19P]  178.1 167.75 0 bottom
JKB  ACES_51522-03001-P01  [ACES_51522-03001-P01_30P]  181.5 11.6 180 bottom
JKBBL  ACES_51522-02001-P02  [ACES_51522-02001-P02_20P]  198.35 11.6 180 bottom
JLAN  SDAN_601029-013231  [SDAN_601029-013231_13P]  214.78 164.98 0 bottom
JLOGO  ACES_50228-01071-P01  [ACES_50228-01071-001_10P]  199.86 157.96 0 top
JP1  PAD-OPEN 43X39  [JUMP_43X39]  157.04 45.85 90 top
JP2  PAD-OPEN 43X39  [JUMP_43X39]  170.19 56.24 270 top
JPCMC  INTEL_CMC_PRIMARY  [INTEL_CMC_PRIMARY_36P-T]  73.97 73.03 0 top
JPWR  ACES_85203-0602N-10  [ACES_85203-0602N-10_6P]  173.66 157.26 180 top
JRTC1  ACES_50271-00201-001  [ACES_50271-00201-001_2P]  258.28 50.39 0 bottom
JSPK  ACES_50278-00601-001  [ACES_50278-00601-001_6P-T]  43.55 12.25 180 bottom
JSSD1  LCN_DAN05-67406-0103  [LCN_DAN05-67406-0103_75P-T]  223.92 45.05 270 bottom
JSSD2  LCN_DAN05-67406-0103  [LCN_DAN05-67406-0103_75P-T]  226.93 21.15 270 bottom
JTAG  ACES_50228-0067N-001  [ACES_50228-0067N-001_6P]  97.61 153.59 90 top
JTP  ACES_51522-01601-P01  [ACES_51522-01601-P01_16P]  213.2 11.6 180 bottom
JUSB1  SDAN_608015-010232  [SDAN_608015-010232_10P]  14.33 49.6 90 bottom
JUSB2  TAITW_PUBAUE-09FLBS1FF4H0  [TAITW_PUBAUE-09FLBS1FF4H0_9P-T]  305.57 66.1 270 bottom
JUSBC1  JAE_DX07S024JJ2  [JAE_DX07S024JJ2_24P-T]  156.5 171.25 0 bottom
JUSBC2  JAE_DX07S024JJ2R1300  [JAE_DX07S024JJ2_24P-T]  312.9 44.92 270 bottom
JWDB  ACES_88266-04001  [ACES_50207-00471-P01_4P-T]  179.04 25.34 90 top
JWLAN  LCN_DAN05-67306-0102  [LCN_DAN05-67306-0102_67P]  301.68 50 90 bottom
LA3  BLM15AG121SN1D_L0402_2P  [MURAT_BLM15AG121SN1D_L0402_2P]  28.22 29.52 0 bottom
LA4  BLM15AG121SN1D_L0402_2P  [MURAT_BLM15AG121SN1D_L0402_2P]  26.78 29.22 315 bottom
LA5  BLM15AG121SN1D_L0402_2P  [MURAT_BLM15AG121SN1D_L0402_2P]  35.13 38.61 90 top
LA6  BLM15BB221SN1D_2P  [MURAT_BLM15BB221SN1D_2P]  29.72 44.45 270 bottom
LA7  BLM15PX330SN1D 0402  [MURAT_BLM15BD601SN1D_2P]  16.2 21.86 0 bottom
LA8  BLM15PX330SN1D 0402  [MURAT_BLM15BD601SN1D_2P]  16.2 16.72 0 bottom
LA9  FBMA-L11-160808-800LMT_2P  [KC_FBMA-L10-160808-800LMT_2P]  14.78 16.56 0 top
LA10  FBMA-L11-160808-800LMT_2P  [KC_FBMA-L10-160808-800LMT_2P]  16.13 22.27 0 top
LA11  BLM15PX330SN1D 0402  [MURAT_BLM15BD601SN1D_2P]  16.77 30.75 0 top
LA12  BLM15PX330SN1D 0402  [MURAT_BLM15BD601SN1D_2P]  16.65 36.02 0 top
LA50  BLM15PX121SN1D_2P  [MURAT_BLM15PX121SN1D_2P]  29.57 14.24 0 bottom
LA51  BLM15PX121SN1D_2P  [MURAT_BLM15PX121SN1D_2P]  28.93 13.37 0 top
LA52  BLM15PX121SN1D_2P  [MURAT_BLM15PX121SN1D_2P]  23.44 13.38 0 top
LA53  BLM15PX121SN1D_2P  [MURAT_BLM15PX121SN1D_2P]  22.04 14.01 180 bottom
LE1  FBMA-L11-160808-800LMT_0603  [KC_FBMA-L11-160808-800LMT_2P]  103.71 3.95 270 top
LE2  FBMA-L11-160808-800LMT_0603  [KC_FBMA-L11-160808-800LMT_2P]  105.98 24.54 180 top
LG1  PBY160808T-301Y-N  [CHILI_PBY160808T-300Y-N_2P]  186.77 98.91 270 top
LG2  PBY160808T-300Y-N_2P  [CHILI_PBY160808T-300Y-N_2P]  191.02 76.3 270 bottom
LG3  PBY160808T-300Y-N_2P  [CHILI_PBY160808T-300Y-N_2P]  177.42 84.16 0 top
LG4  PBY160808T-301Y-N  [CHILI_PBY160808T-300Y-N_2P]  189.5 75 90 bottom
LG5  PBY160808T-300Y-N_2P  [CHILI_PBY160808T-300Y-N_2P]  178.43 91.15 0 top
LG6  PBY160808T-300Y-N_2P  [CHILI_PBY160808T-300Y-N_2P]  192.1 80.02 90 top
LL1  BLM15AG121SN1D_L0402_2P  [MURAT_BLM15AG121SN1D_L0402_2P]  232.71 161.18 180 bottom
LM1  MCM1012B900F06BP_4P  [INPAQ_MCM1012B900F06BP_4P]  134.5 166.48 90 bottom
LT1  0.6UH_MND-04ABIR60M-XGL_20%  [MAG_MND-04ABIR60M-XGL_2P]  141.39 159.85 180 bottom
LT2  MCM1012B900F06BP_4P  [INPAQ_MCM1012B900F06BP_4P]  158.67 163.74 90 bottom
LT3  MCM1012B900F06BP_4P  [INPAQ_MCM1012B900F06BP_4P]  160.26 163.74 90 bottom
LU1  HCM1012GD670A05P  [INPAQ_MCM1012B900F06BP_4P]  299.54 65.35 0 top
LU2  HCM1012GD670A05P  [INPAQ_MCM1012B900F06BP_4P]  299.54 66.81 0 top
LU3  MCM1012B900F06BP_4P  [INPAQ_MCM1012B900F06BP_4P]  21.41 50.11 270 bottom
LU4  HCM1012GD670A05P  [INPAQ_MCM1012B900F06BP_4P]  21.2 56.22 180 top
LU5  HCM1012GD670A05P  [INPAQ_MCM1012B900F06BP_4P]  21.2 54.69 180 top
LU6  MCM1012B900F06BP_4P  [INPAQ_MCM1012B900F06BP_4P]  297.4 68.04 45 top
LU7  HCM1012GD670A05P  [INPAQ_MCM1012B900F06BP_4P]  306.98 44.62 0 bottom
LU8  HCM1012GD670A05P  [INPAQ_MCM1012B900F06BP_4P]  306.98 46.19 0 bottom
LU9  MCM1012B900F06BP_4P  [INPAQ_MCM1012B900F06BP_4P]  304.38 42.39 0 top
LU10  HCM1012GD670A05P  [INPAQ_MCM1012B900F06BP_4P]  306.98 41.07 0 bottom
LU11  HCM1012GD670A05P  [INPAQ_MCM1012B900F06BP_4P]  306.98 43.16 0 bottom
LV2  MCM1012B900F06BP_4P  [INPAQ_MCM1012B900F06BP_4P]  131.67 154.23 180 top
LV3  HCM1012GH900BP_4P  [INPAQ_HCM1012GH900BP_4P-NPM]  184.86 158.47 90 bottom
LV4  HCM1012GH900BP_4P  [INPAQ_HCM1012GH900BP_4P-NPM]  187.91 158.53 90 bottom
LV5  HCM1012GH900BP_4P  [INPAQ_HCM1012GH900BP_4P-NPM]  182.32 158.53 90 bottom
LV6  HCM1012GH900BP_4P  [INPAQ_HCM1012GH900BP_4P-NPM]  180.35 158.66 90 bottom
LX1  PBY100505T-601Y-N_2P  [CHILI_PBY100505T-300Y-N_2P]  187.53 160.05 90 top
LX2  PBY100505T-601Y-N_2P  [CHILI_PBY100505T-300Y-N_2P]  186.32 160.05 90 top
LX3  PBY100505T-601Y-N_2P  [CHILI_PBY100505T-300Y-N_2P]  185.12 160.05 90 top
LX4  PBY100505T-601Y-N_2P  [CHILI_PBY100505T-300Y-N_2P]  183.91 160.05 90 top
LX5  PBY100505T-601Y-N_2P  [CHILI_PBY100505T-300Y-N_2P]  182.7 160.05 90 top
LX6  PBY100505T-601Y-N_2P  [CHILI_PBY100505T-300Y-N_2P]  181.5 160.05 90 top
LX7  PBY100505T-601Y-N_2P  [CHILI_PBY100505T-300Y-N_2P]  180.29 160.05 90 top
LX8  PBY100505T-601Y-N_2P  [CHILI_PBY100505T-300Y-N_2P]  179.08 160.05 90 top
NOREF  -  []  105.59 58.63 270 top
NOREF#2  -  []  314.1 51.6 0 top
NOREF#3  -  []  158.45 7.3 0 top
NOREF#4  -  []  315.2 58 0 top
NOREF#5  -  []  30.15 6.5 0 top
NOREF#6  -  []  90.4 85.4 0 top
NOREF#7  -  []  159.63 74.48 0 top
NOREF#8  -  []  159.4 83.8 0 top
NOREF#9  -  []  222.2 -9.37 0 top
NOREF#10  -  []  170.95 145.8 0 top
NOREF#11  -  []  308.2 58 0 top
NOREF#12  -  []  109.85 165.5 0 top
NOREF#13  -  []  220.65 8 0 top
NOREF#14  -  []  314.1 33 0 top
NOREF#15  -  []  17.16 252.82 0 top
NOREF#16  -  []  114.45 147.3 0 top
NOREF#17  -  []  112.52 -25.76 0 top
NOREF#18  -  []  49.86 55.13 0 top
NOREF#19  -  []  237.95 164.49 0 top
NOREF#20  -  []  11 58 0 top
NOREF#21  -  []  141.53 -41.05 0 top
NOREF#22  -  []  149.82 172.1 0 top
NOREF#23  -  []  126.66 60.04 0 top
NOREF#24  -  []  178.75 68.4 0 top
NOREF#25  -  []  138.75 60.07 0 top
NOREF#26  -  []  168.42 172.1 0 top
NOREF#27  -  []  250.1 53.62 0 top
NOREF#28  -  []  228.55 150.3 0 top
NOREF#29  -  []  307.45 35.8 0 top
NOREF#30  -  []  312.69 80.86 90 top
NOREF#31  -  []  307.45 35.8 0 top
NOREF#32  -  []  4 58 0 top
NOREF#33  -  []  268.15 59.25 0 top
NOREF#34  -  []  211.3 68.4 0 top
NOREF#35  -  []  24.15 6.5 0 top
NOREF#36  -  []  231.65 167.5 0 top
NOREF#37  -  []  112.3 53.24 180 bottom
PBATT1  ACES_50493-0110N-001  [ACES_50493-0110N-001_11P]  64.35 13.98 180 bottom
PC1  1000P_0402_50V7K  [C_0402]  33.79 47.07 180 bottom
PC2  100P_0402_50V8J  [C_0402]  33.79 46.12 180 bottom
PC3  1000P_0402_50V7K  [C_0402]  42 48.21 180 bottom
PC4  100P_0402_50V8J  [C_0402]  42 49.16 180 bottom
PC6  0.022U_0402_25V7K  [C_0402]  71.05 19.26 0 bottom
PC7  0.01UF_0402_25V7K  [C_0402]  71.05 18.37 0 bottom
PC8  1000P_0402_50V7K  [C_0402]  62.67 19.23 180 bottom
PC9  100P_0402_50V8J  [C_0402]  62.67 18.35 180 bottom
PC10  0.22U_0603_25V7K  [C_0603]  50.74 10.66 270 top
PC11  0.1U_0402_25V6  [C_0402]  47.87 12.21 90 top
PC12  .1U_0402_16V7K  [C_0402]  47.83 5.6 270 top
PC13  .1U_0402_16V7K  [C_0402]  81.38 13.9 90 top
PC14  1U_0603_25V6K  [C_0603]  55.7 9.17 180 top
PC100  0.1U_0402_25V6  [C_0402]  45.11 27.79 180 top
PC101  4.7U_0603_6.3V6K  [C_0603]  31.57 26.59 180 bottom
PC102  10U_0805_25V6K~D  [C_0805]  47.99 26.71 0 top
PC103  2200P_0402_50V7K  [C_0402]  49.53 32.94 0 top
PC104  10U_0805_25V6K~D  [C_0805]  45.72 31 180 top
PC105  0.1U_0402_25V6  [C_0402]  34.43 31.15 90 bottom
PC106  0.1U_0402_25V6  [C_0402]  34.48 22.94 90 bottom
PC107  1U_0402_25V6K  [C_0402]  45.68 32.3 180 top
PC108  220U_D2_6.3VY_R15M  [C_D2]  40.03 19.62 0 bottom
PC109  680P_0603_50V8J  [C_0603]  40.96 32.4 0 top
PC110  680P_0603_50V8J  [C_0603]  42.81 19.6 90 top
PC111  4.7U_0603_6.3V6K  [C_0603]  37.73 27.41 90 bottom
PC112  4.7U_0603_6.3V6K  [C_0603]  37.28 21.29 270 bottom
PC113  10U_0805_25V6K~D  [C_0805]  45.76 29.13 180 top
PC114  10U_0805_25V6K~D  [C_0805]  47.88 30.75 0 top
PC115  1000P_0402_50V7K  [C_0402]  49.53 32.05 0 top
PC118  220U_D2_6.3VY_R15M  [C_D2]  44.64 39.51 0 bottom
PC200  0.1U_0402_25V6  [C_0402]  67.47 45.67 270 top
PC201  2200P_0402_50V7K  [C_0402]  68.34 45.67 270 top
PC202  10U_0805_25V6K~D  [C_0805]  69.41 46.56 0 top
PC203  10U_0805_25V6K~D  [C_0805]  69.41 44.59 0 top
PC204  0.1U_0603_25V7K  [C_0603]  64.96 47.58 180 top
PC205  10U_0805_6.3V6K  [C_0805]  63.32 51.18 90 bottom
PC206  10U_0805_6.3V6K  [C_0805]  64.78 51.63 90 top
PC207  1U_0603_10V6K  [C_0603]  61.73 49.13 180 bottom
PC208  1U_0402_25V6K  [C_0402]  65.7 45.66 270 top
PC209  220U_D2 SX_2VY_R9M  [C_D2]  72.04 37.86 180 bottom
PC210  0.033U_0402_16V7K  [C_0402]  61.18 54.21 180 top
PC211  680P_0402_50V7K  [C_0402]  74.13 46.59 180 top
PC212  1U_0603_10V6K  [C_0603]  60.33 47.61 270 bottom
PC213  0.1U_0402_10V7K  [C_0402]  59.25 50.21 0 bottom
PC214  0.1U_0402_10V7K  [C_0402]  59.49 51.45 0 bottom
PC215  220U_D2 SX_2VY_R9M  [C_D2]  72.08 42.75 180 bottom
PC216  1000P_0402_50V7K  [C_0402]  66.59 45.66 270 top
PC217  0.1U_0402_25V6  [C_0402]  56.01 45.17 0 top
PC218  0.1U_0402_25V6  [C_0402]  52.85 47.22 270 top
PC300  0.1U_0402_16V7K  [C_0402]  215.79 21.02 0 top
PC301  0.1U_0402_25V6  [C_0402]  208.09 17.92 270 bottom
PC302  2200P_0402_50V7K  [C_0402]  208.09 18.81 90 bottom
PC303  10U_0805_25V6K~D  [C_0805]  207.89 15.16 0 bottom
PC304  10U_0805_25V6K~D  [C_0805]  205.78 15.16 180 bottom
PC305  0.1U_0603_25V7K  [C_0603]  209.06 18.5 90 top
PC306  220U_D2 SX_2VY_R9M  [C_D2]  192.92 21.22 270 bottom
PC307  220U_D2 SX_2VY_R9M  [C_D2]  188.22 21.22 270 bottom
PC308  1U_0603_6.3V6M  [C_0603]  211.44 20.79 270 bottom
PC309  680P_0402_50V7K  [C_0402]  208.61 24.57 270 bottom
PC310  1U_0402_25V6K  [C_0402]  209.09 17.92 270 bottom
PC311  1000P_0402_50V7K  [C_0402]  209.09 18.81 90 bottom
PC500  330P_0402_50V7K  [C_0402]  91.09 130.64 180 top
PC501  47P_0402_50V8J~D  [C_0402]  91.11 125.93 270 bottom
PC502  0.1U_0402_25V6  [C_0402]  91.1 125.01 90 top
PC503  1U_0402_16V6K  [C_0402]  93.59 129.71 90 top
PC504  0.22U_0603_25V7K  [C_0603]  94.69 129.77 90 top
PC505  68P_0402_50V8J  [C_0402]  90.93 131.53 180 top
PC506  6800P_0402_25V7K  [C_0402]  91.15 132.42 180 top
PC507  1200P_0402_50V7K  [C_0402]  86.6 129.16 270 bottom
PC508  470P_0402_50V7K  [C_0402]  88.39 129.15 180 bottom
PC509  2200P_0402_50V7K  [C_0402]  99.2 129.7 90 bottom
PC510  4700P_0402_25V7K  [C_0402]  100.14 133.26 180 bottom
PC511  .1U_0402_16V7K  [C_0402]  97.48 128.43 90 top
PC512  0.022U_0402_25V7K  [C_0402]  100.14 132.37 180 bottom
PC513  0.01UF_0402_25V7K  [C_0402]  89.92 133.63 0 top
PC514  1500P_0402_50V7K  [C_0402]  101.08 136.02 270 bottom
PC515  0.01UF_0402_25V7K  [C_0402]  97.06 131.66 180 top
PC516  0.15U_0402_16V7K  [C_0402]  88.39 133.09 180 bottom
PC517  0.047U_0402_25V7K  [C_0402]  88.39 133.98 180 bottom
PC518  2200P_0402_50V7K  [C_0402]  88.44 135.77 270 bottom
PC519  330P_0402_50V7K  [C_0402]  96.42 136.76 180 top
PC520  68P_0402_50V8J  [C_0402]  94.93 134.39 0 top
PC521  2200P_0402_50V7K  [C_0402]  96.74 132.55 180 top
PC522  680P_0402_50V7K  [C_0402]  100.14 137.79 180 bottom
PC523  .1U_0402_16V7K  [C_0402]  87.54 137.53 0 bottom
PC524  0.022U_0402_25V7K  [C_0402]  97.08 138.16 90 bottom
PC525  0.022U_0402_25V7K  [C_0402]  87.73 135.12 0 top
PC526  0.022U_0402_25V7K  [C_0402]  95.24 138.09 90 top
PC527  0.022U_0402_25V7K  [C_0402]  94.35 138.09 90 top
PC528  0.022U_0402_25V7K  [C_0402]  87.73 134.23 0 top
PC529  .1U_0402_16V7K  [C_0402]  97.03 140 0 bottom
PC530  0.033U_0402_16V7K  [C_0402]  92.32 139.07 270 top
PC531  0.22U_0402_16V7K  [C_0402]  93.21 139.07 270 top
PC532  2200P_0402_50V7K  [C_0402]  94.34 139.06 0 bottom
PC533  470P_0402_50V7K  [C_0402]  93.22 139.95 180 bottom
PC534  0.01UF_0402_25V7K  [C_0402]  94.63 136.75 270 top
PC535  330P_0402_50V7K  [C_0402]  90.91 134.5 90 top
PC536  68P_0402_50V8J  [C_0402]  92.28 134.97 270 top
PC537  680P_0402_50V7K  [C_0402]  90.55 139.95 180 bottom
PC538  6800P_0402_25V7K  [C_0402]  93.75 135.85 180 top
PC539  33U_D2_25VM_R40M  [C_EEFCX1E330R]  106.4 126.79 0 bottom
PC540  1U_0402_6.3V6K  [C_0402]  129.93 135.41 90 top
PC541  0.22U_0603_16V7K  [C_0603]  132.11 138.39 270 bottom
PC542  33U_D2_25VM_R40M  [C_EEFCX1E330R]  98.4 122.03 0 bottom
PC543  10U_0805_25V6K~D  [C_0805]  132.04 134.06 270 top
PC544  10U_0805_25V6K~D  [C_0805]  133.75 134.06 270 top
PC545  10U_0805_25V6K~D  [C_0805]  132.06 135.21 90 top
PC546  0.1U_0402_25V6  [C_0402]  134.25 135.12 90 top
PC547  2200P_0402_50V7K  [C_0402]  133.37 135.12 90 top
PC548  33P_0603_50V8J  [C_0603]  133.55 126.92 0 top
PC549  1U_0402_6.3V6K  [C_0402]  138.44 135.29 90 top
PC550  0.22U_0603_16V7K  [C_0603]  140.63 138.31 270 bottom
PC551  10U_0805_25V6K~D  [C_0805]  140.53 134.01 270 top
PC552  10U_0805_25V6K~D  [C_0805]  142.26 134.01 270 top
PC553  10U_0805_25V6K~D  [C_0805]  140.48 135.16 90 top
PC554  0.1U_0402_25V6  [C_0402]  142.68 135.09 90 top
PC555  2200P_0402_50V7K  [C_0402]  141.82 135.09 90 top
PC556  33P_0603_50V8J  [C_0603]  141.74 126.92 0 top
PC557  1U_0402_6.3V6K  [C_0402]  147.54 135.74 180 top
PC558  0.22U_0603_16V7K  [C_0603]  148.59 138.36 270 bottom
PC559  10U_0805_25V6K~D  [C_0805]  148.83 135.18 90 top
PC560  10U_0805_25V6K~D  [C_0805]  150.26 134.04 270 top
PC561  10U_0805_25V6K~D  [C_0805]  148.5 134.04 270 top
PC562  0.1U_0402_25V6  [C_0402]  150.13 135.04 90 top
PC563  2200P_0402_50V7K  [C_0402]  151.02 135.04 90 top
PC564  33P_0603_50V8J  [C_0603]  149.62 126.92 0 top
PC565  10U_0805_25V6K~D  [C_0805]  115.52 135.18 90 top
PC566  1U_0402_6.3V6K  [C_0402]  113.49 135.35 90 top
PC567  0.22U_0603_16V7K  [C_0603]  115.65 138.32 270 bottom
PC568  10U_0805_25V6K~D  [C_0805]  115.57 134 270 top
PC569  10U_0805_25V6K~D  [C_0805]  117.28 134 270 top
PC570  680P_0603_50V7K  [C_0603]  117.49 126.73 0 top
PC571  0.1U_0402_25V6  [C_0402]  117.73 135.09 90 top
PC572  2200P_0402_50V7K  [C_0402]  116.87 135.09 90 top
PC573  1U_0402_6.3V6K  [C_0402]  121.81 135.41 90 top
PC574  0.22U_0603_16V7K  [C_0603]  123.98 138.41 270 bottom
PC575  10U_0805_25V6K~D  [C_0805]  123.77 134.09 270 top
PC576  10U_0805_25V6K~D  [C_0805]  125.52 134.09 270 top
PC577  10U_0805_25V6K~D  [C_0805]  123.77 135.25 90 top
PC578  0.1U_0402_25V6  [C_0402]  125.05 135.17 90 top
PC579  2200P_0402_50V7K  [C_0402]  125.92 135.17 90 top
PC580  680P_0603_50V7K  [C_0603]  125.11 126.85 0 top
PC581  2200P_0402_50V7K  [C_0402]  156.49 124.99 180 top
PC582  0.1U_0402_25V6  [C_0402]  158.32 127.74 270 top
PC583  10U_0805_25V6K~D  [C_0805]  159.65 128.26 270 top
PC584  10U_0805_25V6K~D  [C_0805]  157.2 131.66 180 top
PC585  10U_0805_25V6K~D  [C_0805]  156.5 129.9 180 top
PC586  0.22U_0603_16V7K  [C_0603]  155.69 132.01 270 bottom
PC587  680P_0603_50V7K  [C_0603]  152.03 122.52 90 top
PC588  4.7U_0402_6.3V6M  [C_0402]  153.75 128.43 90 top
PC589  2200P_0402_50V7K  [C_0402]  88.03 107.61 270 top
PC590  0.22U_0402_10V6K  [C_0402]  95 107.72 0 bottom
PC591  680P_0603_50V7K  [C_0603]  94.31 97.52 0 bottom
PC592  10U_0805_25V6K  [C_0805]  90.29 110.2 0 bottom
PC593  0.1U_0603_25V7K  [C_0603]  89.86 103.23 0 bottom
PC594  0.1U_0402_25V6  [C_0402]  88.91 107.61 270 top
PC596  22U_0603_6.3V6M  [C_0603]  94.25 96.12 0 bottom
PC597  22U_0603_6.3V6M  [C_0603]  91.13 93.58 180 bottom
PC598  22U_0603_6.3V6M  [C_0603]  93.1 93.58 0 bottom
PC599  22U_0603_6.3V6M  [C_0603]  94.25 94.85 0 bottom
PC701  0.1U_0402_25V6  [C_0402]  51.31 47.45 90 top
PC702  0.047U_0402_25V7K  [C_0402]  59.58 30.79 270 top
PC703  0.1U_0402_25V6  [C_0402]  54.74 25.73 180 top
PC704  2200P_0402_50V7K  [C_0402]  56.9 25.82 0 top
PC705  10U_0805_25V6K~D  [C_0805]  56.71 27.19 0 top
PC706  10U_0805_25V6K~D  [C_0805]  55 27.19 180 top
PC707  0.1U_0603_25V7K  [C_0603]  56.59 40.66 270 bottom
PC708  0.1U_0402_25V6  [C_0402]  57.66 39.27 0 bottom
PC709  0.01UF_0402_25V7K  [C_0402]  59.5 39.27 0 bottom
PC710  2.2U_0603_16V6K  [C_0603]  57.86 30.97 270 bottom
PC711  1U_0603_25V6K  [C_0603]  60.65 29.57 90 top
PC712  22U_0805_25V6M  [C_0805]  71.34 27.68 90 bottom
PC713  22U_0805_25V6M  [C_0805]  69.62 27.68 90 bottom
PC714  22U_0805_25V6M  [C_0805]  67.9 27.7 90 bottom
PC715  680P_0402_50V7K  [C_0402]  50.37 23.78 90 top
PC716  0.1U_0402_25V6  [C_0402]  51.96 32.52 90 top
PC717  0.1U_0402_25V6  [C_0402]  52.85 33.35 90 top
PC718  100P_0402_50V8J  [C_0402]  62.18 38.83 270 top
PC719  0.01UF_0402_25V7K  [C_0402]  62.22 35.96 0 bottom
